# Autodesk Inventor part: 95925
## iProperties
Author: Administrator
Shininess: 64.0
Angle Display Precision: 2
Document Length Units: 11272
Document Angle Units: 11286
Document Time Units: 11279
Document Mass Units: 11290
Document Length Units Precision: 3
Document Angle Units Precision: 2
Compacted: True
PropertySet Name: _Private Model Information
Created: 2002-04
Part Number: 95925
Material: Stainless Steel, 440C
Document SubType Name: Modeling
Designer: Administrator
Control State: 0
Master: False
Checked Out: False
PropertySet Name: Design Tracking Control
Density: 0.0
Volumn: 0.0
Area: 0.0
PropertySet Name: Model Information
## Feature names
1. Revolution1
